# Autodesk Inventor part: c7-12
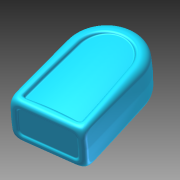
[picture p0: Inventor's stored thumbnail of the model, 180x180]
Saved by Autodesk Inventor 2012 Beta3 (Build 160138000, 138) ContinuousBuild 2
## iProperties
Created: 2010-12
Part Number: c7-12
Material: Default
Document SubType Name: Modeling
Designer: Beta-8540w
Density: 1 g/cm^3
Author: Beta-8540w
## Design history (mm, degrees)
sketch "Sketch1"
  geometry: L1 (-25, 0)-(25, 0); L2 (25, 0)-(25, 80); L3 (25, 80)-(-25, 80); L4 (-25, 80)-(-25, 0); 2 further points
  constraints: 8 end point, 2 parallel, 1 coincident, 1 horizontal, 1 midpoint, 1 perpendicular
  dimensions: "d0" = 50 distance of L3.end L2.end; "d1" = 80 distance of L2.end L1.end
extrude "Extrusion1" new body sketch "Sketch1" distance "d2" = 15; taper "d3" = 0 deg
feature "FaceDraft1" dims angle "d4" = -2 deg
fillet "Fillet1"
fillet "Fillet2" dims "d5" = 8, "d6" = 8, "d7" = 8, "d8" = 8, "d9" = 8, "d10" = 8, "d11" = 3, "d12" = 3, "d13" = 3, "d14" = 6, "d15" = 5
sketch "Sketch2"
  geometry: L1 (5.522, 12)-(38.474, 12) reference; L2 (0, 0)-(43.996, 0) reference; L3 (41.757, 6.83)-(41.995, 0); L4 (41.925, 2)-(2.071, 2); L5 (2.001, 0)-(2.24, 6.83); L6 (5.522, 10)-(38.474, 10); A1 r 5.284 centre (38.474, 6.716) between (43.755, 6.9) and (38.474, 12) reference; A2 r 5.284 centre (5.522, 6.716) between (5.522, 12) and (0.241, 6.9) reference; A3 r 3.284 centre (38.474, 6.716) between (41.757, 6.83) and (38.474, 10); A4 r 3.284 centre (5.522, 6.716) between (5.522, 10) and (2.24, 6.83); 1 further point
  constraints: 8 end point, 4 point on circle, 4 point on line, 2 centre point, 1 other
  dimensions: "d16" = 2 radial gap between concentric circles of A2 A4
extrude "Extrusion2" cut sketch "Sketch2" distance "d17" = 1; taper "d18" = 0 deg
feature "FaceDraft2" dims angle "d19" = 15 deg
sketch "Sketch3" dims "d20" = 2.5
  geometry: L1 (16.476, 3)-(-16.476, 3) reference; L2 (16.476, 5.5)-(-16.476, 5.5); 9 further points
  constraints: 2 end point, 2 parallel, 1 horizontal alignment, 19 other
extrude "Extrusion3" cut sketch "Sketch3" distance "d21" = 3; taper "d22" = 0 deg
feature "FaceDraft3" dims angle "d23" = 10 deg
workplane "Work Plane1"
sketch "Sketch4"
  geometry: L1 (41.1, -1.222)-(41.476, -12) reference; L2 (41.476, -12)-(-8.524, -12) reference; L3 (-8.524, -12)-(-8.147, -1.222) reference; L4 (-3.776, 3)-(-1.272, 3) reference; L5 (-0.743, 0)-(33.695, 0) reference; L6 (34.225, 3)-(36.728, 3) reference; L7 (-11.024, -1.856)-(43.976, -1.856); A1 r 100 centre (16.476, -98) between (43.976, -1.856) and (-11.024, -1.856); 2 further points
  constraints: 2 end point, 2 point on circle, 1 centre point, 1 midpoint, 1 parallel, 1 vertical alignment, 4 other
  dimensions: "d25" = 100 radius of A1; "d26" = 14 distance edge to line of A1 L2; "d27" = 55 distance of L7.start L7.end
extrude_surface "ExtrusionSrf1" sketch "Sketch4" dims "d28" = 86, "d29" = 0
feature "Replace Face1"
fillet "Fillet3" dims "d34" = 1, "d35" = 2
mirror "Mirror1"
fillet "Fillet4" dims "d36" = 20
body "Solid1"
body "Srf1"
node "Project Cut Edges1"
